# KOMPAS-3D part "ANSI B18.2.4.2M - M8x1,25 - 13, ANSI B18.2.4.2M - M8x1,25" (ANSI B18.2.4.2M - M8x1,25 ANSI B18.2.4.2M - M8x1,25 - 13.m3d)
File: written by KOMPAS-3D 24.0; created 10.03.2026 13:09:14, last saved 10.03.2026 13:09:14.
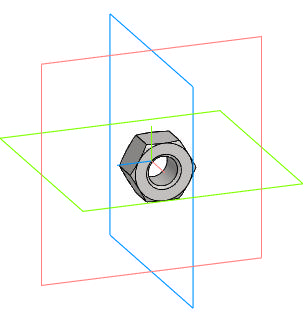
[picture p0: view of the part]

Document properties: Автор: R2D2; Полное имя файла: E:\Работа\Зайцев\BV3232P(4pc)-FP-3WL-F-ISO-H Кран шаровой DN.ru Ду15-100 Ру16\DN80\исходные материалы\ANSI B18.2.4.2M - M8x1,25 ANSI B18.2.4.2M - M8x1,25 - 13.m3d

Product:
- Body: Solid1  | qty 1
- Part/product: ANSI B18.2.4.2M - M8x1,25 - 13  | designation ANSI B18.2.4.2M - M8x1,25
    Комментарий: Типы метрических   шестигранных гаек   2
    additional columns: Сталь, мягкая

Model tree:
1. Solid1  (labels: Solid1)

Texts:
  ANSI B18.2.4.2M - M8x1,25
